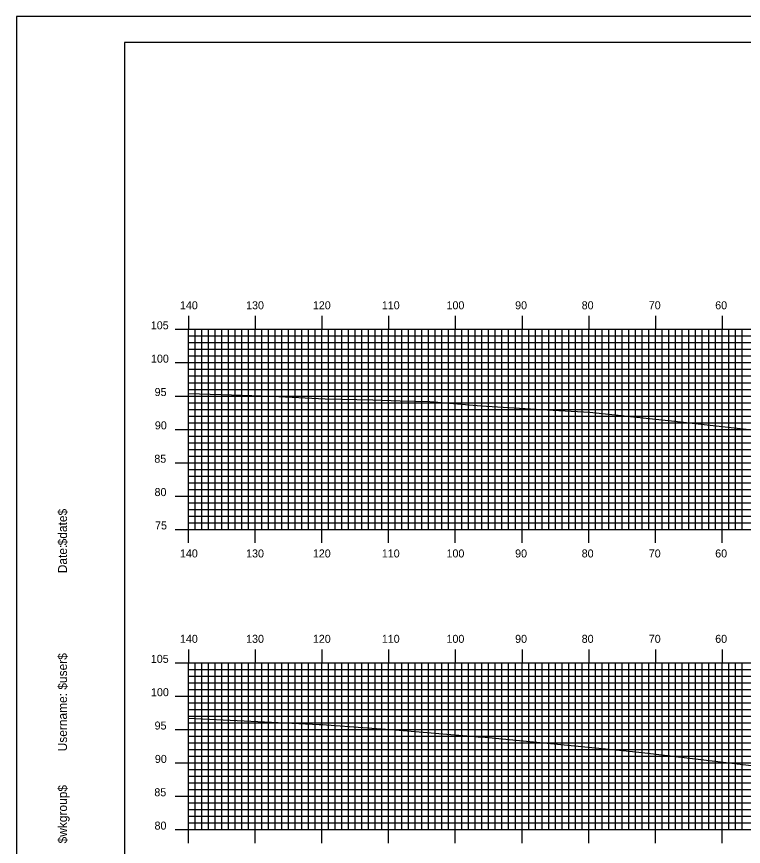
# Model space of a CAD drawing. Extents: x 1775564 to 1775907, y 442591 to 442811.
# Drawn here: x 1775563.9 to 1775672.9, y 442686.2 to 442810.5 of the extents above; entities that cross this region are included whole.
import ezdxf

# ---------------------------------------------------------------- set-up
doc = ezdxf.new("R2010")
doc.units = 0
for name, color, linetype in [('BORDER', 7, 'Continuous'), ('H_V ANNOTATION', 7, 'Continuous'), ('MAJOR', 7, 'Continuous'), ('MINOR', 7, 'Continuous'), ('PLOT BOUNDARY', 7, 'Continuous'), ('S_Roadway_Centerline', 7, 'Continuous')]:
    doc.layers.add(name, color=color, linetype=linetype)

msp = doc.modelspace()

# ---------------------------------------------------------------- linework, layer by layer
at = {"layer": 'BORDER'}
msp.add_lwpolyline([(1775580.11, 442596.67), (1775900.11, 442596.67), (1775900.11, 442806.67), (1775580.11, 442806.67)], close=True, dxfattribs=at)
at = {"layer": 'MAJOR'}
for p, q in [((1775589.71, 442765.67), (1775589.71, 442763.67)), ((1775599.71, 442765.67), (1775599.71, 442763.67)), ((1775609.71, 442765.67), (1775609.71, 442763.67)), ((1775619.71, 442765.67), (1775619.71, 442763.67)), ((1775629.71, 442765.67), (1775629.71, 442763.67)), ((1775639.71, 442765.67), (1775639.71, 442763.67)), ((1775649.71, 442765.67), (1775649.71, 442763.67)), ((1775659.71, 442765.67), (1775659.71, 442763.67)), ((1775669.71, 442765.67), (1775669.71, 442763.67)), ((1775587.71, 442763.67), (1775589.71, 442763.67)), ((1775589.71, 442763.67), (1775869.71, 442763.67)), ((1775589.71, 442733.67), (1775589.71, 442763.67)), ((1775589.71, 442733.67), (1775589.71, 442763.67)), ((1775589.71, 442763.67), (1775869.71, 442763.67)), ((1775599.71, 442733.67), (1775599.71, 442763.67)), ((1775609.71, 442733.67), (1775609.71, 442763.67)), ((1775619.71, 442733.67), (1775619.71, 442763.67)), ((1775629.71, 442733.67), (1775629.71, 442763.67)), ((1775639.71, 442733.67), (1775639.71, 442763.67)), ((1775649.71, 442733.67), (1775649.71, 442763.67)), ((1775659.71, 442733.67), (1775659.71, 442763.67)), ((1775669.71, 442733.67), (1775669.71, 442763.67)), ((1775587.71, 442758.67), (1775589.71, 442758.67)), ((1775589.71, 442758.67), (1775869.71, 442758.67)), ((1775587.71, 442753.67), (1775589.71, 442753.67)), ((1775589.71, 442753.67), (1775869.71, 442753.67)), ((1775587.71, 442748.67), (1775589.71, 442748.67)), ((1775589.71, 442748.67), (1775869.71, 442748.67)), ((1775587.71, 442743.67), (1775589.71, 442743.67)), ((1775589.71, 442743.67), (1775869.71, 442743.67)), ((1775587.71, 442738.67), (1775589.71, 442738.67)), ((1775589.71, 442738.67), (1775869.71, 442738.67)), ((1775587.71, 442733.67), (1775589.71, 442733.67)), ((1775589.71, 442733.67), (1775869.71, 442733.67)), ((1775589.71, 442733.67), (1775869.71, 442733.67)), ((1775589.71, 442731.66), (1775589.71, 442733.67)), ((1775599.71, 442731.66), (1775599.71, 442733.67)), ((1775609.71, 442731.66), (1775609.71, 442733.67)), ((1775619.71, 442731.66), (1775619.71, 442733.67)), ((1775629.71, 442731.66), (1775629.71, 442733.67)), ((1775639.71, 442731.66), (1775639.71, 442733.67)), ((1775649.71, 442731.66), (1775649.71, 442733.67)), ((1775659.71, 442731.66), (1775659.71, 442733.67)), ((1775669.71, 442731.66), (1775669.71, 442733.67)), ((1775589.71, 442715.67), (1775589.71, 442713.67)), ((1775599.71, 442715.67), (1775599.71, 442713.67)), ((1775609.71, 442715.67), (1775609.71, 442713.67)), ((1775619.71, 442715.67), (1775619.71, 442713.67)), ((1775629.71, 442715.67), (1775629.71, 442713.67)), ((1775639.71, 442715.67), (1775639.71, 442713.67)), ((1775649.71, 442715.67), (1775649.71, 442713.67)), ((1775659.71, 442715.67), (1775659.71, 442713.67)), ((1775669.71, 442715.67), (1775669.71, 442713.67)), ((1775587.71, 442713.67), (1775589.71, 442713.67)), ((1775589.71, 442713.67), (1775869.71, 442713.67)), ((1775589.71, 442688.67), (1775589.71, 442713.67)), ((1775589.71, 442688.67), (1775589.71, 442713.67)), ((1775589.71, 442713.67), (1775869.71, 442713.67)), ((1775599.71, 442688.67), (1775599.71, 442713.67)), ((1775609.71, 442688.67), (1775609.71, 442713.67)), ((1775619.71, 442688.67), (1775619.71, 442713.67)), ((1775629.71, 442688.67), (1775629.71, 442713.67)), ((1775639.71, 442688.67), (1775639.71, 442713.67)), ((1775649.71, 442688.67), (1775649.71, 442713.67)), ((1775659.71, 442688.67), (1775659.71, 442713.67)), ((1775669.71, 442688.67), (1775669.71, 442713.67)), ((1775587.71, 442708.67), (1775589.71, 442708.67)), ((1775589.71, 442708.67), (1775869.71, 442708.67)), ((1775587.71, 442703.67), (1775589.71, 442703.67)), ((1775589.71, 442703.67), (1775869.71, 442703.67)), ((1775587.71, 442698.67), (1775589.71, 442698.67)), ((1775589.71, 442698.67), (1775869.71, 442698.67)), ((1775587.71, 442693.67), (1775589.71, 442693.67)), ((1775589.71, 442693.67), (1775869.71, 442693.67)), ((1775587.71, 442688.67), (1775589.71, 442688.67)), ((1775589.71, 442688.67), (1775869.71, 442688.67)), ((1775589.71, 442688.67), (1775869.71, 442688.67)), ((1775589.71, 442686.66), (1775589.71, 442688.67)), ((1775599.71, 442686.66), (1775599.71, 442688.67)), ((1775609.71, 442686.66), (1775609.71, 442688.67)), ((1775619.71, 442686.66), (1775619.71, 442688.67)), ((1775629.71, 442686.66), (1775629.71, 442688.67)), ((1775639.71, 442686.66), (1775639.71, 442688.67)), ((1775649.71, 442686.66), (1775649.71, 442688.67)), ((1775659.71, 442686.66), (1775659.71, 442688.67)), ((1775669.71, 442686.66), (1775669.71, 442688.67))]:
    msp.add_line(p, q, dxfattribs=at)
at = {"layer": 'MINOR'}
for p, q in [((1775590.71, 442733.67), (1775590.71, 442763.67)), ((1775591.71, 442733.67), (1775591.71, 442763.67)), ((1775592.71, 442733.67), (1775592.71, 442763.67)), ((1775593.71, 442733.67), (1775593.71, 442763.67)), ((1775594.71, 442733.67), (1775594.71, 442763.67)), ((1775595.71, 442733.67), (1775595.71, 442763.67)), ((1775596.71, 442733.67), (1775596.71, 442763.67)), ((1775597.71, 442733.67), (1775597.71, 442763.67)), ((1775598.71, 442733.67), (1775598.71, 442763.67)), ((1775600.71, 442733.67), (1775600.71, 442763.67)), ((1775601.71, 442733.67), (1775601.71, 442763.67)), ((1775602.71, 442733.67), (1775602.71, 442763.67)), ((1775603.71, 442733.67), (1775603.71, 442763.67)), ((1775604.71, 442733.67), (1775604.71, 442763.67)), ((1775605.71, 442733.67), (1775605.71, 442763.67)), ((1775606.71, 442733.67), (1775606.71, 442763.67)), ((1775607.71, 442733.67), (1775607.71, 442763.67)), ((1775608.71, 442733.67), (1775608.71, 442763.67)), ((1775610.71, 442733.67), (1775610.71, 442763.67)), ((1775611.71, 442733.67), (1775611.71, 442763.67)), ((1775612.71, 442733.67), (1775612.71, 442763.67)), ((1775613.71, 442733.67), (1775613.71, 442763.67)), ((1775614.71, 442733.67), (1775614.71, 442763.67)), ((1775615.71, 442733.67), (1775615.71, 442763.67)), ((1775616.71, 442733.67), (1775616.71, 442763.67)), ((1775617.71, 442733.67), (1775617.71, 442763.67)), ((1775618.71, 442733.67), (1775618.71, 442763.67)), ((1775620.71, 442733.67), (1775620.71, 442763.67)), ((1775621.71, 442733.67), (1775621.71, 442763.67)), ((1775622.71, 442733.67), (1775622.71, 442763.67)), ((1775623.71, 442733.67), (1775623.71, 442763.67)), ((1775624.71, 442733.67), (1775624.71, 442763.67)), ((1775625.71, 442733.67), (1775625.71, 442763.67)), ((1775626.71, 442733.67), (1775626.71, 442763.67)), ((1775627.71, 442733.67), (1775627.71, 442763.67)), ((1775628.71, 442733.67), (1775628.71, 442763.67)), ((1775630.71, 442733.67), (1775630.71, 442763.67)), ((1775631.71, 442733.67), (1775631.71, 442763.67)), ((1775632.71, 442733.67), (1775632.71, 442763.67)), ((1775633.71, 442733.67), (1775633.71, 442763.67)), ((1775634.71, 442733.67), (1775634.71, 442763.67)), ((1775635.71, 442733.67), (1775635.71, 442763.67)), ((1775636.71, 442733.67), (1775636.71, 442763.67)), ((1775637.71, 442733.67), (1775637.71, 442763.67)), ((1775638.71, 442733.67), (1775638.71, 442763.67)), ((1775640.71, 442733.67), (1775640.71, 442763.67)), ((1775641.71, 442733.67), (1775641.71, 442763.67)), ((1775642.71, 442733.67), (1775642.71, 442763.67)), ((1775643.71, 442733.67), (1775643.71, 442763.67)), ((1775644.71, 442733.67), (1775644.71, 442763.67)), ((1775645.71, 442733.67), (1775645.71, 442763.67)), ((1775646.71, 442733.67), (1775646.71, 442763.67)), ((1775647.71, 442733.67), (1775647.71, 442763.67)), ((1775648.71, 442733.67), (1775648.71, 442763.67)), ((1775650.71, 442733.67), (1775650.71, 442763.67)), ((1775651.71, 442733.67), (1775651.71, 442763.67)), ((1775652.71, 442733.67), (1775652.71, 442763.67)), ((1775653.71, 442733.67), (1775653.71, 442763.67)), ((1775654.71, 442733.67), (1775654.71, 442763.67)), ((1775655.71, 442733.67), (1775655.71, 442763.67)), ((1775656.71, 442733.67), (1775656.71, 442763.67)), ((1775657.71, 442733.67), (1775657.71, 442763.67)), ((1775658.71, 442733.67), (1775658.71, 442763.67)), ((1775660.71, 442733.67), (1775660.71, 442763.67)), ((1775661.71, 442733.67), (1775661.71, 442763.67)), ((1775662.71, 442733.67), (1775662.71, 442763.67)), ((1775663.71, 442733.67), (1775663.71, 442763.67)), ((1775664.71, 442733.67), (1775664.71, 442763.67)), ((1775665.71, 442733.67), (1775665.71, 442763.67)), ((1775666.71, 442733.67), (1775666.71, 442763.67)), ((1775667.71, 442733.67), (1775667.71, 442763.67)), ((1775668.71, 442733.67), (1775668.71, 442763.67)), ((1775670.71, 442733.67), (1775670.71, 442763.67)), ((1775671.71, 442733.67), (1775671.71, 442763.67)), ((1775672.71, 442733.67), (1775672.71, 442763.67)), ((1775589.71, 442762.67), (1775869.71, 442762.67)), ((1775589.71, 442762.67), (1775591.72, 442762.67)), ((1775589.71, 442761.67), (1775869.71, 442761.67)), ((1775589.71, 442761.67), (1775591.72, 442761.67)), ((1775589.71, 442760.67), (1775869.71, 442760.67)), ((1775589.71, 442760.67), (1775591.72, 442760.67)), ((1775589.71, 442759.67), (1775869.71, 442759.67)), ((1775589.71, 442759.67), (1775591.72, 442759.67)), ((1775589.71, 442757.67), (1775869.71, 442757.67)), ((1775589.71, 442757.67), (1775591.72, 442757.67)), ((1775589.71, 442756.67), (1775869.71, 442756.67)), ((1775589.71, 442756.67), (1775591.72, 442756.67)), ((1775589.71, 442755.67), (1775869.71, 442755.67)), ((1775589.71, 442755.67), (1775591.72, 442755.67)), ((1775589.71, 442754.67), (1775869.71, 442754.67)), ((1775589.71, 442754.67), (1775591.72, 442754.67)), ((1775589.71, 442752.67), (1775869.71, 442752.67)), ((1775589.71, 442752.67), (1775591.72, 442752.67)), ((1775589.71, 442751.67), (1775869.71, 442751.67)), ((1775589.71, 442751.67), (1775591.72, 442751.67)), ((1775589.71, 442750.67), (1775869.71, 442750.67)), ((1775589.71, 442750.67), (1775591.72, 442750.67)), ((1775589.71, 442749.67), (1775869.71, 442749.67)), ((1775589.71, 442749.67), (1775591.72, 442749.67)), ((1775589.71, 442747.67), (1775869.71, 442747.67)), ((1775589.71, 442747.67), (1775591.72, 442747.67)), ((1775589.71, 442746.67), (1775869.71, 442746.67)), ((1775589.71, 442746.67), (1775591.72, 442746.67)), ((1775589.71, 442745.67), (1775869.71, 442745.67)), ((1775589.71, 442745.67), (1775591.72, 442745.67)), ((1775589.71, 442744.67), (1775869.71, 442744.67)), ((1775589.71, 442744.67), (1775591.72, 442744.67)), ((1775589.71, 442742.67), (1775869.71, 442742.67)), ((1775589.71, 442742.67), (1775591.72, 442742.67)), ((1775589.71, 442741.67), (1775869.71, 442741.67)), ((1775589.71, 442741.67), (1775591.72, 442741.67)), ((1775589.71, 442740.67), (1775869.71, 442740.67)), ((1775589.71, 442740.67), (1775591.72, 442740.67)), ((1775589.71, 442739.67), (1775869.71, 442739.67)), ((1775589.71, 442739.67), (1775591.72, 442739.67)), ((1775589.71, 442737.67), (1775869.71, 442737.67)), ((1775589.71, 442737.67), (1775591.72, 442737.67)), ((1775589.71, 442736.67), (1775869.71, 442736.67)), ((1775589.71, 442736.67), (1775591.72, 442736.67)), ((1775589.71, 442735.67), (1775869.71, 442735.67)), ((1775589.71, 442735.67), (1775591.72, 442735.67)), ((1775589.71, 442734.67), (1775869.71, 442734.67)), ((1775589.71, 442734.67), (1775591.72, 442734.67)), ((1775590.71, 442688.67), (1775590.71, 442713.67)), ((1775591.71, 442688.67), (1775591.71, 442713.67)), ((1775592.71, 442688.67), (1775592.71, 442713.67)), ((1775593.71, 442688.67), (1775593.71, 442713.67)), ((1775594.71, 442688.67), (1775594.71, 442713.67)), ((1775595.71, 442688.67), (1775595.71, 442713.67)), ((1775596.71, 442688.67), (1775596.71, 442713.67)), ((1775597.71, 442688.67), (1775597.71, 442713.67)), ((1775598.71, 442688.67), (1775598.71, 442713.67)), ((1775600.71, 442688.67), (1775600.71, 442713.67)), ((1775601.71, 442688.67), (1775601.71, 442713.67)), ((1775602.71, 442688.67), (1775602.71, 442713.67)), ((1775603.71, 442688.67), (1775603.71, 442713.67)), ((1775604.71, 442688.67), (1775604.71, 442713.67)), ((1775605.71, 442688.67), (1775605.71, 442713.67)), ((1775606.71, 442688.67), (1775606.71, 442713.67)), ((1775607.71, 442688.67), (1775607.71, 442713.67)), ((1775608.71, 442688.67), (1775608.71, 442713.67)), ((1775610.71, 442688.67), (1775610.71, 442713.67)), ((1775611.71, 442688.67), (1775611.71, 442713.67)), ((1775612.71, 442688.67), (1775612.71, 442713.67)), ((1775613.71, 442688.67), (1775613.71, 442713.67)), ((1775614.71, 442688.67), (1775614.71, 442713.67)), ((1775615.71, 442688.67), (1775615.71, 442713.67)), ((1775616.71, 442688.67), (1775616.71, 442713.67)), ((1775617.71, 442688.67), (1775617.71, 442713.67)), ((1775618.71, 442688.67), (1775618.71, 442713.67)), ((1775620.71, 442688.67), (1775620.71, 442713.67)), ((1775621.71, 442688.67), (1775621.71, 442713.67)), ((1775622.71, 442688.67), (1775622.71, 442713.67)), ((1775623.71, 442688.67), (1775623.71, 442713.67)), ((1775624.71, 442688.67), (1775624.71, 442713.67)), ((1775625.71, 442688.67), (1775625.71, 442713.67)), ((1775626.71, 442688.67), (1775626.71, 442713.67)), ((1775627.71, 442688.67), (1775627.71, 442713.67)), ((1775628.71, 442688.67), (1775628.71, 442713.67)), ((1775630.71, 442688.67), (1775630.71, 442713.67)), ((1775631.71, 442688.67), (1775631.71, 442713.67)), ((1775632.71, 442688.67), (1775632.71, 442713.67)), ((1775633.71, 442688.67), (1775633.71, 442713.67)), ((1775634.71, 442688.67), (1775634.71, 442713.67)), ((1775635.71, 442688.67), (1775635.71, 442713.67)), ((1775636.71, 442688.67), (1775636.71, 442713.67)), ((1775637.71, 442688.67), (1775637.71, 442713.67)), ((1775638.71, 442688.67), (1775638.71, 442713.67)), ((1775640.71, 442688.67), (1775640.71, 442713.67)), ((1775641.71, 442688.67), (1775641.71, 442713.67)), ((1775642.71, 442688.67), (1775642.71, 442713.67)), ((1775643.71, 442688.67), (1775643.71, 442713.67)), ((1775644.71, 442688.67), (1775644.71, 442713.67)), ((1775645.71, 442688.67), (1775645.71, 442713.67)), ((1775646.71, 442688.67), (1775646.71, 442713.67)), ((1775647.71, 442688.67), (1775647.71, 442713.67)), ((1775648.71, 442688.67), (1775648.71, 442713.67)), ((1775650.71, 442688.67), (1775650.71, 442713.67)), ((1775651.71, 442688.67), (1775651.71, 442713.67)), ((1775652.71, 442688.67), (1775652.71, 442713.67)), ((1775653.71, 442688.67), (1775653.71, 442713.67)), ((1775654.71, 442688.67), (1775654.71, 442713.67)), ((1775655.71, 442688.67), (1775655.71, 442713.67)), ((1775656.71, 442688.67), (1775656.71, 442713.67)), ((1775657.71, 442688.67), (1775657.71, 442713.67)), ((1775658.71, 442688.67), (1775658.71, 442713.67)), ((1775660.71, 442688.67), (1775660.71, 442713.67)), ((1775661.71, 442688.67), (1775661.71, 442713.67)), ((1775662.71, 442688.67), (1775662.71, 442713.67)), ((1775663.71, 442688.67), (1775663.71, 442713.67)), ((1775664.71, 442688.67), (1775664.71, 442713.67)), ((1775665.71, 442688.67), (1775665.71, 442713.67)), ((1775666.71, 442688.67), (1775666.71, 442713.67)), ((1775667.71, 442688.67), (1775667.71, 442713.67)), ((1775668.71, 442688.67), (1775668.71, 442713.67)), ((1775670.71, 442688.67), (1775670.71, 442713.67)), ((1775671.71, 442688.67), (1775671.71, 442713.67)), ((1775672.71, 442688.67), (1775672.71, 442713.67)), ((1775589.71, 442712.67), (1775869.71, 442712.67)), ((1775589.71, 442712.67), (1775591.72, 442712.67)), ((1775589.71, 442711.67), (1775869.71, 442711.67)), ((1775589.71, 442711.67), (1775591.72, 442711.67)), ((1775589.71, 442710.67), (1775869.71, 442710.67)), ((1775589.71, 442710.67), (1775591.72, 442710.67)), ((1775589.71, 442709.67), (1775869.71, 442709.67)), ((1775589.71, 442709.67), (1775591.72, 442709.67)), ((1775589.71, 442707.67), (1775869.71, 442707.67)), ((1775589.71, 442707.67), (1775591.72, 442707.67)), ((1775589.71, 442706.67), (1775869.71, 442706.67)), ((1775589.71, 442706.67), (1775591.72, 442706.67)), ((1775589.71, 442705.67), (1775869.71, 442705.67)), ((1775589.71, 442705.67), (1775591.72, 442705.67)), ((1775589.71, 442704.67), (1775869.71, 442704.67)), ((1775589.71, 442704.67), (1775591.72, 442704.67)), ((1775589.71, 442702.67), (1775869.71, 442702.67)), ((1775589.71, 442702.67), (1775591.72, 442702.67)), ((1775589.71, 442701.67), (1775869.71, 442701.67)), ((1775589.71, 442701.67), (1775591.72, 442701.67)), ((1775589.71, 442700.67), (1775869.71, 442700.67)), ((1775589.71, 442700.67), (1775591.72, 442700.67)), ((1775589.71, 442699.67), (1775869.71, 442699.67)), ((1775589.71, 442699.67), (1775591.72, 442699.67)), ((1775589.71, 442697.67), (1775869.71, 442697.67)), ((1775589.71, 442697.67), (1775591.72, 442697.67)), ((1775589.71, 442696.67), (1775869.71, 442696.67)), ((1775589.71, 442696.67), (1775591.72, 442696.67)), ((1775589.71, 442695.67), (1775869.71, 442695.67)), ((1775589.71, 442695.67), (1775591.72, 442695.67)), ((1775589.71, 442694.67), (1775869.71, 442694.67)), ((1775589.71, 442694.67), (1775591.72, 442694.67)), ((1775589.71, 442692.67), (1775869.71, 442692.67)), ((1775589.71, 442692.67), (1775591.72, 442692.67)), ((1775589.71, 442691.67), (1775869.71, 442691.67)), ((1775589.71, 442691.67), (1775591.72, 442691.67)), ((1775589.71, 442690.67), (1775869.71, 442690.67)), ((1775589.71, 442690.67), (1775591.72, 442690.67)), ((1775589.71, 442689.67), (1775869.71, 442689.67)), ((1775589.71, 442689.67), (1775591.72, 442689.67))]:
    msp.add_line(p, q, dxfattribs=at)
at = {"layer": 'PLOT BOUNDARY'}
msp.add_lwpolyline([(1775563.92, 442590.55), (1775903.92, 442590.55), (1775903.92, 442810.55), (1775563.92, 442810.55)], close=True, dxfattribs=at)
at = {"layer": 'S_Roadway_Centerline'}
for points in [[(1775589.71, 442754.03), (1775594.6, 442753.89), (1775602.24, 442753.66), (1775610.2, 442753.27), (1775617.34, 442753.09), (1775621.44, 442752.95), (1775625.9, 442752.83), (1775633.58, 442752.18), (1775640.99, 442751.76), (1775645.22, 442751.51), (1775649.87, 442751.23), (1775662.6, 442749.9), (1775667.04, 442749.42), (1775672.88, 442748.75), (1775679.81, 442747.94)], [(1775589.71, 442705.4), (1775598.07, 442704.99), (1775609.31, 442704.44), (1775609.85, 442704.42), (1775610.37, 442704.4), (1775621.29, 442703.6), (1775632.03, 442702.69), (1775633.14, 442702.6), (1775634.21, 442702.54), (1775654.85, 442700.54), (1775657.73, 442700.24), (1775675.77, 442698.08)]]:
    msp.add_lwpolyline(points, dxfattribs=at)

# ---------------------------------------------------------------- texts
at = {"layer": 'BORDER'}
for s, p in [('$date$', (1775571.48, 442731.28)), ('Date:', (1775571.48, 442727.1)), ('$user$', (1775571.48, 442709.65)), ('Username:', (1775571.48, 442700.4)), ('$wkgroup$', (1775571.48, 442686.6))]:
    msp.add_text(s, height=1.339, rotation=90, dxfattribs=at).set_placement(p)
at = {"layer": 'H_V ANNOTATION'}
for s, p in [('140', (1775588.42, 442766.67)), ('130', (1775598.34, 442766.67)), ('120', (1775608.35, 442766.67)), ('110', (1775618.69, 442766.67)), ('100', (1775628.39, 442766.67)), ('90', (1775638.68, 442766.67)), ('80', (1775648.66, 442766.67)), ('70', (1775658.72, 442766.67)), ('60', (1775668.68, 442766.67)), ('105', (1775584.05, 442763.67)), ('100', (1775584.08, 442758.67)), ('95', (1775584.62, 442753.67)), ('90', (1775584.66, 442748.67)), ('85', (1775584.58, 442743.67)), ('80', (1775584.61, 442738.67)), ('75', (1775584.69, 442733.67)), ('140', (1775588.42, 442729.47)), ('130', (1775598.34, 442729.47)), ('120', (1775608.35, 442729.47)), ('110', (1775618.69, 442729.47)), ('100', (1775628.39, 442729.47)), ('90', (1775638.68, 442729.47)), ('80', (1775648.66, 442729.47)), ('70', (1775658.72, 442729.47)), ('60', (1775668.68, 442729.47)), ('140', (1775588.42, 442716.67)), ('130', (1775598.34, 442716.67)), ('120', (1775608.35, 442716.67)), ('110', (1775618.69, 442716.67)), ('100', (1775628.39, 442716.67)), ('90', (1775638.68, 442716.67)), ('80', (1775648.66, 442716.67)), ('70', (1775658.72, 442716.67)), ('60', (1775668.68, 442716.67)), ('105', (1775584.05, 442713.67)), ('100', (1775584.08, 442708.67)), ('95', (1775584.62, 442703.67)), ('90', (1775584.66, 442698.67)), ('85', (1775584.58, 442693.67)), ('80', (1775584.61, 442688.67))]:
    msp.add_text(s, height=1.2, dxfattribs=at).set_placement(p)
at = {"layer": 'MAJOR'}
for p in [(1775589.7, 442733.67), (1775589.7, 442688.67)]:
    msp.add_text('-', height=0.012, dxfattribs=at).set_placement(p)

doc.saveas('drawing.dxf')
